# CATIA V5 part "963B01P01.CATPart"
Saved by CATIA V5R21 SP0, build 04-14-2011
Part number: 963B01P01
Bounding box of the stored display mesh (mm): x -33.4 to 33.4, y -127 to 127, z -8 to 9
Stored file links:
  C:\Users\ALI OZGUN\Desktop\alhan\963B01P01.CATPart
  C:\Users\ALI OZGUN\Desktop\alhan\943B01P01.CATPart
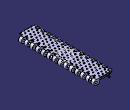
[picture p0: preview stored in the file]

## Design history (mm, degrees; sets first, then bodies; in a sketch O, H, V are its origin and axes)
Body1 (main body)
Body2
  Sketch1 on zx-plane, origin (0, 0, 0), H (-1, 0, 0), V (0, 0, 1)
    construction line L1 (25.4, 8) -> (25.4, -8)
    line L2 (25.4, -8) -> (-25.4, -8)
    construction line L3 (-25.4, -8) -> (-25.4, 8)
    line L4 (-25.4, 8) -> (25.4, 8)
    point P3 (-25.4, -8)
    arc A1 centre (25.4, 0) radius 8 from (25.4, 8) to (25.4, -8) cw
    arc A2 centre (-25.4, 0) radius 8 from (-25.4, 8) to (-25.4, -8) ccw
    point P7 (-25.4, -8)
    length L4 = 50.8
    length L3 = 16
    vertical: L1 V, L3 V
    horizontal: L2 H, L4 H
    equidistance: L1 L3 O, L2 L4 O
    tangency: A1 L2, A2 L4, A2 L2, L4 A1
    coincidence: P7 L2, P3 P7
  Pad1: profile Sketch1, direction (0, 1, 0), length 127, mirrored extent
  Body3
    Sketch2 on face of Pad1 from Sketch1.L4, origin (0, 0, 8), H (1, 0, 0), V (0, 1, 0)
      line L1 (19.4, 118) -> (45.1506, 118)
      line L2 (45.1506, 118) -> (45.1506, 108.9)
      line L3 (45.1506, 108.9) -> (19.4, 108.9)
      line L4 (19.4, 108.9) -> (19.4, 118)
      reference projected line E1 (-25.4, 127) -> (25.4, 127) from edge [face of Pad1 from Sketch1.L4 | end face of Pad1]
      reference projected line E2 through (25.4, 0) direction (0, 1) from axis of face of Pad1 from Sketch1.A2
      distance L1 E1 = 9
      distance E2 L4 = 6
      distance L3 L1 = 9.1
      horizontal: L1 H, L3 H
      vertical: L2 V, L4 V
    Pad2: profile Sketch2, direction (0, 0, -1), length 18, mirrored extent
    RectPattern1: of Pad2, direction 1 instances 15, spacing 18.1, along axis of face of Pad1 from Sketch1.A2 reversed
  Remove1: tool Body3
  Body4
    Solid1: linked copy from another document
    Symmetry1: Reference yz-plane, ToTransfor Solid1
    Translate1: Direction edge [face of Pad1 from Sketch1.A2 | face of Pad1 from Sketch1.L4], Length 9.05, ToTransfor Symmetry1
  Remove2: tool Body4
  Sketch3 on zx-plane, origin (0, 0, 0), H (-1, 0, 0), V (0, 0, 1)
    circle A1 centre (25.4, 0) radius 3.15
    circle A2 centre (-25.4, 0) radius 3.15
    reference projected arc E1 centre (25.4, 0) radius 8 from (25.4, -8) to (25.4, 8) ccw from edge [face of Pad1 from Sketch1.A1 | face of Solid1]
    reference projected arc E2 centre (-25.4, 0) radius 8 from (-25.4, 8) to (-25.4, -8) ccw from edge [face of Pad1 from Sketch1.A2 | end face of Pad1]
    radius A1 = 3.15
    radius A2 = 3.15
    concentricity: A1 E1, A2 E2
  Pocket1: profile Sketch3, direction (0, -1, 0), length 204, mirrored extent
  Body5
    Sketch4 on face of Pad1 from Sketch1.L4, origin (0, 0, 8), H (1, 0, 0), V (0, 1, 0)
      circle A1 centre (11, 122.2) radius 2
      point P1 (11, 122.2)
      circle A2 centre (0, 122.2) radius 2
      point P2 (0, 122.2)
      circle A3 centre (-11, 122.2) radius 2
      point P3 (-11, 122.2)
      reference projected line E1 (-25.4, 127) -> (25.4, 127) from edge [face of Pad1 from Sketch1.L4 | end face of Pad1]
      radius A1 = 2
      radius A2 = 2
      radius A3 = 2
      distance P3 P2 = 11
      distance P3 P2 V = 0
      distance P2 P1 V = 0
      distance P1 P2 = 11
      distance V P2 = 0
      distance E1 P1 = 4.8
    Pad3: profile Sketch4, direction (0, 0, 1), length 1
    Sketch5 on face of Pad1 from Sketch1.L4, origin (0, 0, 8), H (1, 0, 0), V (0, 1, 0)
      circle A1 centre (5.5, 113.15) radius 2
      point P1 (5.5, 113.15)
      circle A2 centre (16.5, 113.15) radius 2
      point P2 (16.5, 113.15)
      circle A3 centre (-5.5, 113.15) radius 2
      point P3 (-5.5, 113.15)
      circle A4 centre (-16.5, 113.15) radius 2
      point P4 (-16.5, 113.15)
      axis line L1 (-31.102, 113.15) -> (46.1463, 113.15)
      reference projected line E1 (-19.4, 117.95) -> (-25.4, 117.95) from edge [face of Solid1 | face of Pad1 from Sketch1.L4]
      radius A2 = 2
      radius A1 = 2
      radius A3 = 2
      radius A4 = 2
      distance P1 P3 = 11
      distance P2 P1 = 11
      distance P3 V = 5.5
      distance P4 P3 = 11
      distance L1 P4 = 0
      distance L1 E1 = 4.8
      horizontal: L1 H
      coincidence: P3 L1, P1 L1, P2 L1
    Pad4: profile Sketch5, direction (0, 0, 1), length 1
    RectPattern2: of the body so far, direction 1 instances 13, spacing 20, along edge [face of Solid1 | face of Pad1 from Sketch1.L4]
    Sketch6 on start face of Pad1, origin (0, -127, 0), H (1, 0, 0), V (0, 0, 1)
      point P5 (17.4, 0)
      point P6 (-17.4, 0)
      line L1 (17.4, 0) -> (17.4, 0.2)
      line L2 (-17.4, 0) -> (-17.4, 0.2)
      line L3 (15.4, 2.2) -> (5.5215, 2.2)
      line L4 (3.5325, 0.4091) -> (2.9836, -4.8136)
      arc A1 centre (0, -4.5) radius 3 from (2.9836, -4.8136) to (-2.9836, -4.8136) cw
      point P8 (0, -4.5)
      line L5 (-2.9836, -4.8136) -> (-3.5325, 0.4091)
      point P10 (-3.7207, 2.2)
      line L6 (-5.5215, 2.2) -> (-15.4, 2.2)
      reference projected line E1 (-25.4, 8) -> (25.4, 8) from edge [start face of Pad1 | face of Pad1 from Sketch1.L4]
      reference projected line E2 (25.4, -8) -> (-25.4, -8) from edge [start face of Pad1 | face of Pad1 from Sketch1.L2]
      construction line L7 (38.4335, 0) -> (33.4, 0)
      point P11 (38.4335, 0)
      axis line L8 (-33.4, 0) -> (-39.1937, 0)
      arc A2 centre (-15.4, 0.2) radius 2 from (-15.4, 2.2) to (-17.4, 0.2) ccw
      arc A3 centre (5.5215, 0.2) radius 2 from (5.5215, 2.2) to (3.5325, 0.4091) ccw
      arc A4 centre (15.4, 0.2) radius 2 from (15.4, 2.2) to (17.4, 0.2) cw
      arc A5 centre (-5.5215, 0.2) radius 2 from (-3.5325, 0.4091) to (-5.5215, 2.2) ccw
      line L9 (33.4, 0) -> (46.3888, 0)
      line L10 (-33.4, 0) -> (-48.9583, 0)
      construction arc A6 centre (-25.4, 0) radius 8 from (-25.4, 8) to (-25.4, -8) ccw
      arc A7 centre (-25.4, 0) radius 8 from (-33.4, 0) to (-17.4, 0) ccw
      construction arc A8 centre (25.4, 0) radius 8 from (25.4, -8) to (25.4, 8) ccw
      arc A9 centre (25.4, 0) radius 8 from (17.4, 0) to (33.4, 0) ccw
      angle L5 V = 6
      radius A1 = 3
      distance L3 E1 = 5.8
      distance A1 E2 = 0.5
      radius A2 = 2
      radius A3 = 2 {= Sketch6.radius(A2)}
      radius A4 = 2 {= Sketch6.radius(A2)}
      radius A5 = 2 {= Sketch6.radius(A2)}
      coincidence: P5 H, P6 H, P10 L3, P8 V, P11 H, L5 P10, L6 P10
      tangency: L1 A8, L2 A6, A1 L4, L5 A1, A2 L6, A2 L2, A3 L3, A3 L4, A4 L3, A4 L1, A5 L5, A5 L6
      horizontal: L3 H, L6 H, L7 H, L8 H, L9 H, L10 H
      symmetry: L4 L5 V
    Sketch7 on face of Pad1 from Sketch1.L4, origin (0, 0, 8), H (1, 0, 0), V (0, 1, 0)
      line L1 (35.409, -143.7774) -> (-39.1047, -143.7774)
      line L2 (-39.1047, -143.7774) -> (-39.1047, -125.5844)
      line L3 (-39.1047, -125.5844) -> (35.409, -125.5844)
      line L4 (35.409, -125.5844) -> (35.409, -143.7774)
      horizontal: L1 H, L3 H
      vertical: L2 V, L4 V
    Pocket2: profile Sketch7, direction (0, 0, -1), length 1, mirrored extent
  Assemble1: tool Body5
  Sketch8 on face of Pad1 from Sketch1.L4, origin (0, 0, 8), H (1, 0, 0), V (0, 1, 0)
    line L1 (64.4244, -249.7045) -> (-67.602, -249.7045)
    line L2 (-67.602, -249.7045) -> (-67.602, -73)
    line L3 (-67.602, -73) -> (64.4244, -73)
    line L4 (64.4244, -73) -> (64.4244, -249.7045)
    reference intersected line E1 (-45.1506, -73) -> (-19.4, -73) from face of Solid1
    horizontal: L1 H, L3 H
    vertical: L2 V, L4 V
    coincidence: L3 E1
  Pocket3: profile Sketch8, direction (0, 0, -1), length -68, mirrored extent, deactivated
  Body6
    Solid2: solid without history
  Remove3: tool Body6
  Body7
    Solid3: solid without history
    Translate2: Direction yz-plane, ToTransfor Solid3, Length 101.6
  Remove4: tool Body7
  Body8
    Solid4: solid without history
  Remove5: tool Body8
  Sketch9 on zx-plane, origin (0, 0, 0), H (-1, 0, 0), V (0, 0, 1)
    line L1 (0, 72) -> (0, 6.9718)
    point P1 (0, 72)
    reference projected line E1 (-25.4, -8) -> (25.4, -8) from edge [face of Pad1 from Sketch1.L2 | end face of Pad1]
    distance P1 E1 = 80
    coincidence: P1 V
    vertical: L1 V
Body9 "BOSALTMA_ALANI"
  Solid5: solid without history
  Translate3: Direction yz-plane, Length 101.6, ToTransfor Solid5
  Body10
    Solid6: solid without history
  Add1: tool Body10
